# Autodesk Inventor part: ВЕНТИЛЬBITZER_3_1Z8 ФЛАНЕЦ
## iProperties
Created: 2011-02
Part Number: ВЕНТИЛЬBITZER_3_1Z8 ФЛАНЕЦ
Document SubType Name: Modeling
Designer: Чернышев Юрий
Mass: 416.835 g
Surface Area: 584.907 cm^2
Volume: 416.835 cm^3
Density: 1 g/cm^3
Author: Чернышев Юрий
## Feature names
1. ExtrusionBlind1
2. Hole1
3. Hole2
4. Hole3
5. Hole4
6. Hole5
